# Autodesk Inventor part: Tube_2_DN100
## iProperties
Shininess: 64.0
Length Units: 11269
Angle Units: 11279
Time Units: 11290
Mass Units: 11283
Length Display Precision: 3
Angle Display Precision: 2
Compacted: True
Part Number: Tube_2_DN100
Document SubType Name: Modeling
Created: 2008-04
Material: Par défaut
Designer: plup
Density: 0.0
Volumn: 0.0
Area: 0.0
PropertySet Name: Model Information
Control State: 0
Master: False
Checked Out: False
MATIERE_PIECE: X2CrNi 18-11
OBSERVATIONS: Lg.: .......
DESIGNATION: Tube 2
Author: plup
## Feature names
1. Extrusion1
